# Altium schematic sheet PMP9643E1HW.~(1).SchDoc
size 431 x 279 mm; Date: Not shown in title block; ApprovedBy: Not shown in title block; CheckedBy: Not shown in title block; Author: Not shown in title block; CompanyName: Not shown in title block; Engineer: Not shown in title block; Organization: Not shown in title block; Address1: Not shown in title block; Address2: Not shown in title block; Address3: Not shown in title block; Address4: Not shown in title block; DocumentNumber: 1; Revision: Use project parameter SCH_Rev; SheetNumber: 1; SheetTotal: 1; PageSetup: Record=PageOptions|CenterHorizontal=True|CenterVertical=True|PrintScale=1.00|XCorrection=1.00|YCorrection=1.00|PrintKind=0|BorderSize=5000000|LeftOffset=0|BottomOffset=0|Orientation=2|PaperLength=1000|PaperWidth=1000|Scale=100|PaperSource=15|PrintQuality=600|MediaType=1|DitherType=10|PaperKind=Letter|PrintScaleMode=1
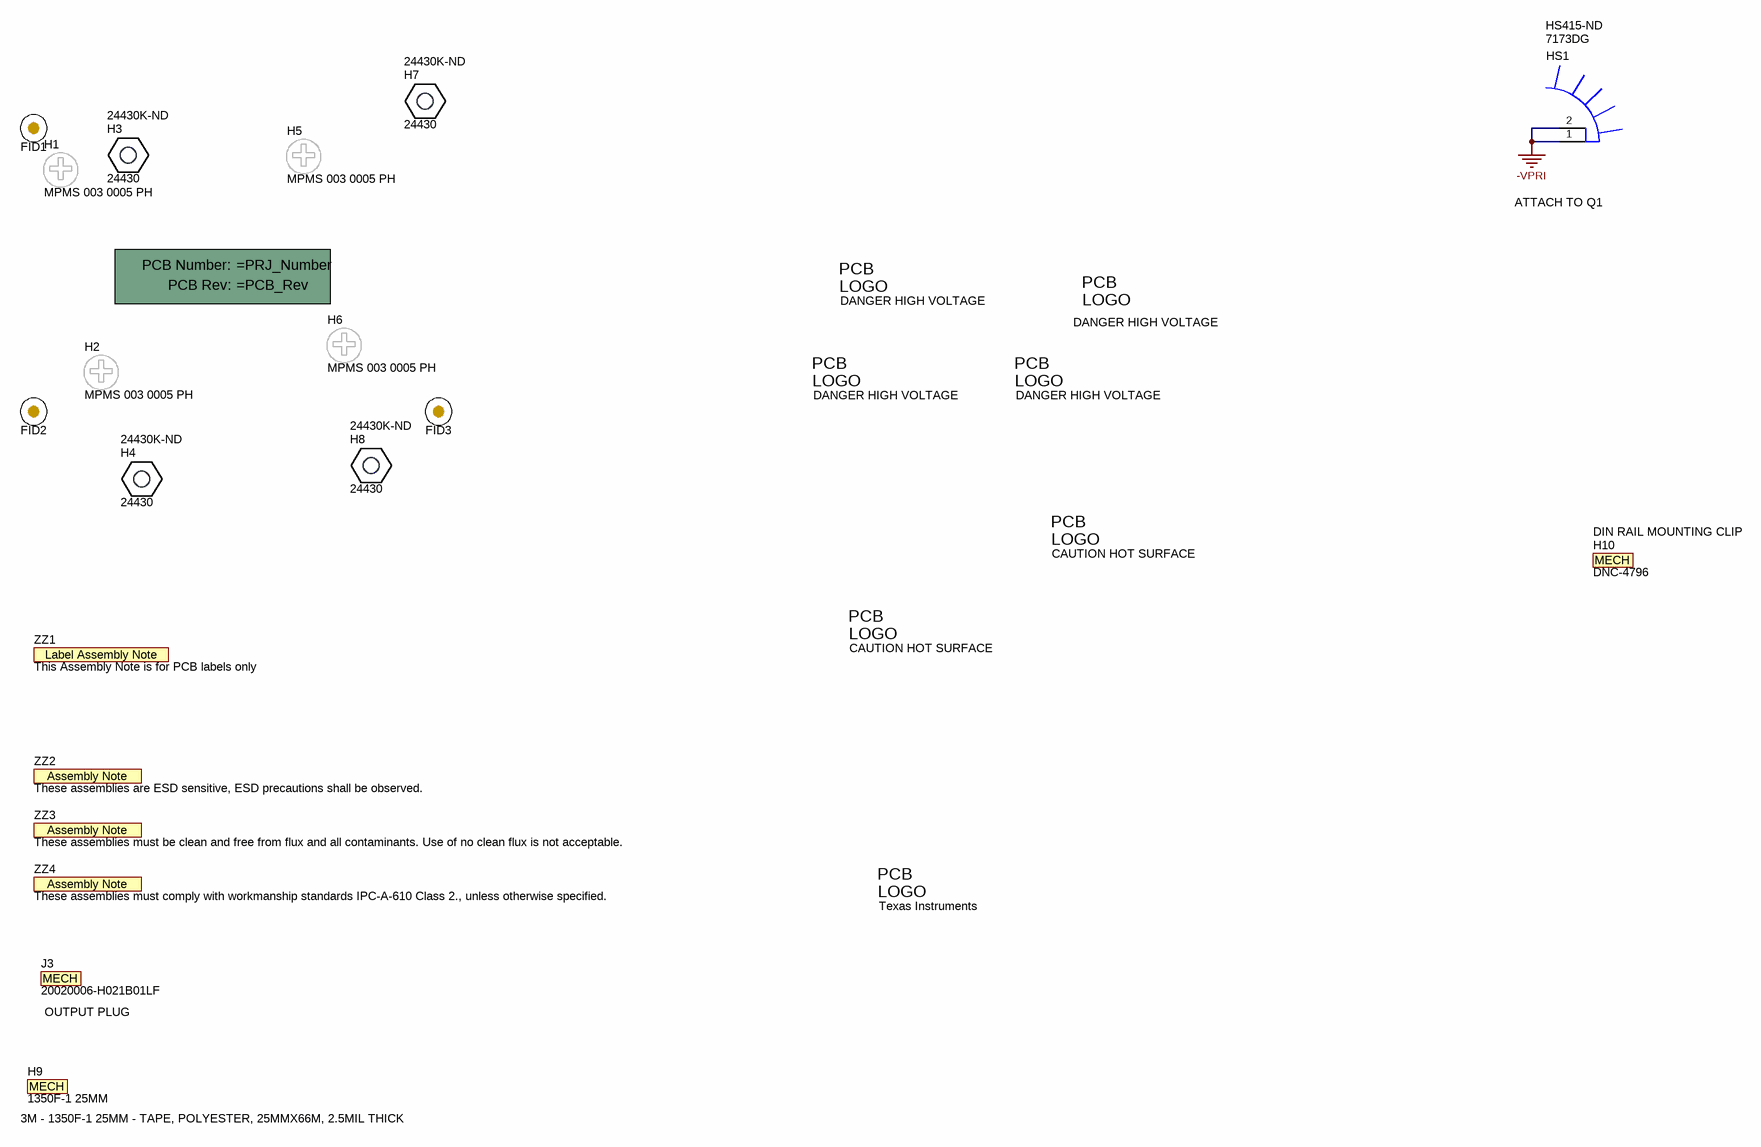
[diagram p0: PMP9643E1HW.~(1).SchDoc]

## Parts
!PCB1  Printed Circuit Board  (value not drawn)  (mechanical)
FID1  Fiducial  [Fiducial10-20]  (value not drawn)
FID2  Fiducial  [Fiducial10-20]  (value not drawn)
FID3  Fiducial  [Fiducial10-20]  (value not drawn)
H1  MPMS 003 0005 PH  [BuildingFastener_MPMS_003_0005_PH]
H2  MPMS 003 0005 PH  [BuildingFastener_MPMS_003_0005_PH]
H3  24430  Supplier Part Number: 24430K-ND  [Keystone_24430]
H4  24430  Supplier Part Number: 24430K-ND  [Keystone_24430]
H5  MPMS 003 0005 PH  [BuildingFastener_MPMS_003_0005_PH]
H6  MPMS 003 0005 PH  [BuildingFastener_MPMS_003_0005_PH]
H7  24430  Supplier Part Number: 24430K-ND  [Keystone_24430]
H8  24430  Supplier Part Number: 24430K-ND  [Keystone_24430]
H9  1350F-1 25MM  Description: 3M - 1350F-1 25MM - TAPE, POLYESTER, 25MMX66M, 2.5MIL THICK  (mechanical)
H10  DNC-4796  Description: DIN RAIL MOUNTING CLIP  (mechanical)
HS1  7173DG  Supplier Part Number 1: HS415-ND  [HSINK_7173DG]
J3  20020006-H021B01LF  (mechanical)
Logo2  DANGER HIGH VOLTAGE  [IEC_HighVoltage_Small]  (no BOM)
Logo3  DANGER HIGH VOLTAGE  [IEC_HighVoltage_Small]  (no BOM)
Logo4  DANGER HIGH VOLTAGE  [IEC_HighVoltage_Small]  (no BOM)
Logo5  CAUTION HOT SURFACE  [IEC_HotSurface_Small]  (no BOM)
Logo7  Texas Instruments  [TI_Stacked_Overlay_Medium]  (no BOM)
Logo8  DANGER HIGH VOLTAGE  [IEC_HighVoltage_Small]  (no BOM)
Logo9  CAUTION HOT SURFACE  [IEC_HotSurface_Small]  (no BOM)
ZZ1  This Assembly Note is for PCB labels only  [AssemblyNoteLabel]  (no BOM)
ZZ2  These assemblies are ESD sensitive, ESD precautions shall be observed.  [AssemblyNote]  (no BOM)
ZZ3  These assemblies must be clean and free from flux and all contaminants. Use of no clean flux is not acceptable.  [AssemblyNote]  (no BOM)
ZZ4  These assemblies must comply with workmanship standards IPC-A-610 Class 2., unless otherwise specified.  [AssemblyNote]  (no BOM)

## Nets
-VPRI: HS1.1 HS1.2

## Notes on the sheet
- ATTACH TO Q1
- (near J3) OUTPUT PLUG

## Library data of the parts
!PCB1 = PCB: Manufacturer: Any; SymbolCreator: a0412235
FID1-FID3 = Fiducial: Fiducial mark.  There is nothing to buy or mount.; SymbolCreator: codlsc
H1 H2 H5 H6 = MPMS 003 0005 PH: MACHINE SCREW PAN PHILLIPS M3; Manufacturer: B&F Fastener Supply; CompType: Hardware
H3 H4 H7 H8 = 1902C: HEX STANDOFF M3 ALUMINUM 5MM; Manufacturer: Keystone Electronics; Threaded/Unthreaded: Threaded; Gender: Female, Female; Thread/Screw/Hole Size: M3 Thread; Between Board Height: 0.197" (5.00mm); Plating: Iridite
H9 = MechPart: Will add component to BOM.  Useful for cables, nuts, etc. not in libraries; Manufacturer: 3M; SymbolCreator: codlsc; CompType: Mechanical; U/M: EA; Material Thickness: 0.063; TaMax_C: 130; Reel Length (Metric): 66; Reel Length (Imperial): 217; External Width: 25
H10 = MechPart: Will add component to BOM.  Useful for cables, nuts, etc. not in libraries; Manufacturer: Bud Industries; For Use With/Related Products: Din Rail Track; Accessory Type: DIN Clip
HS1 = 7173DG: BOARD LEVEL HEATSINK .375" TO-220; Manufacturer: Aavid Thermalloy; Attachment Method: Bolt On and PC Pin; Material Finish: Tin; Thermal Resistance @ Natural: 25.8°C/W; Thermal Resistance @ Forced Air Flow: 10.0°C/W @ 200 LFM; Power Dissipation @ Temperature Rise: 1.5W @ 50°C; Shape: Rectangular
J3 = 20020006-H021B01LF: TERM BLOCK PLUG 2POS 5.08MM; Manufacturer: FCI; SymbolCreator: codlsc
Logo2-Logo4 Logo8 = IEC_HighVoltage: IEC 61010-1 High Voltage Warning; SymbolCreator: codlsc
Logo5 Logo9 = IEC_HotSurface: IEC 61010-1 Hot Surface Warning; SymbolCreator: codlsc
Logo7 = TI_Logo: Texas Instrument Corporate Signature; SymbolCreator: codlsc
ZZ1 = AssemblyNoteLabel: SymbolCreator: a0412235
ZZ2-ZZ4 = AssemblyNote: SymbolCreator: codlsc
